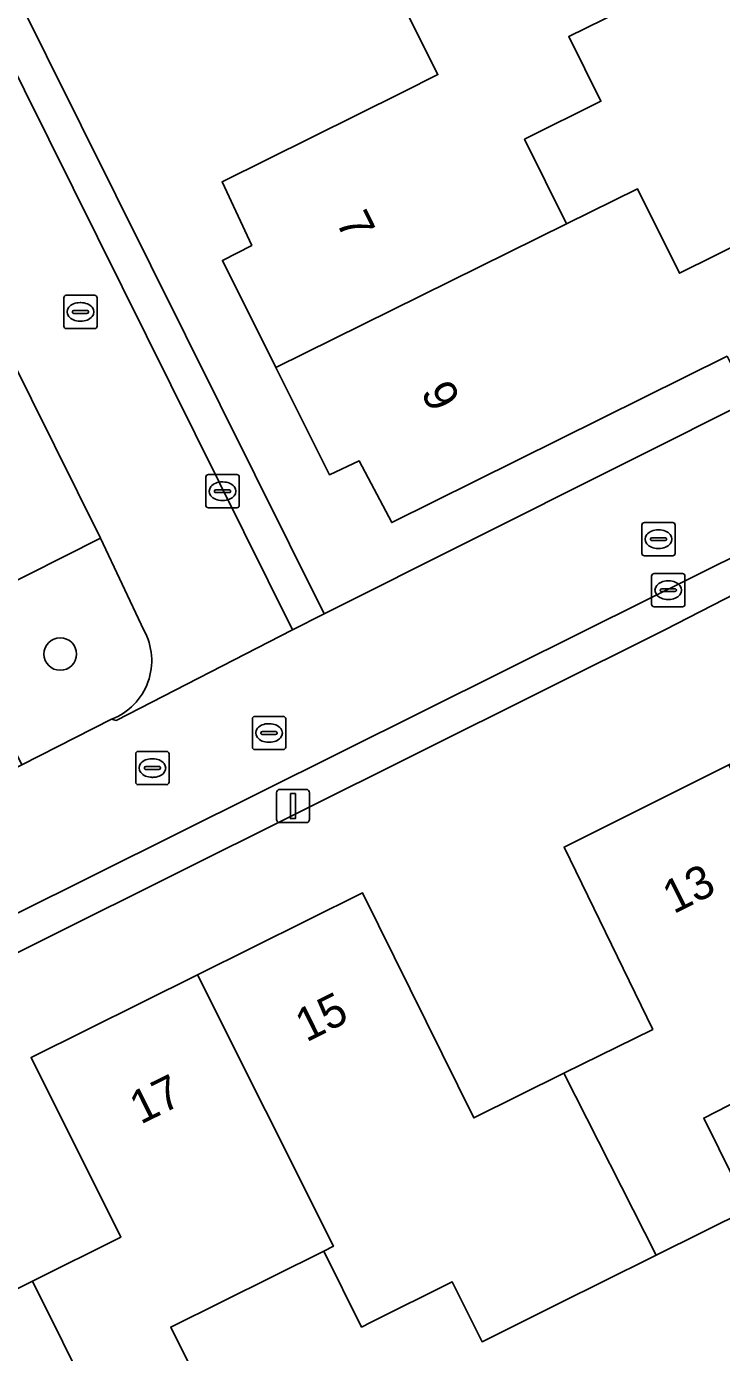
# Model space of a CAD drawing. Extents: x 157320 to 158835, y 386650 to 388491.
# Drawn here: x 157624.59 to 157645.47, y 387728.28 to 387768.13 of the extents above; entities that cross this region are included whole.
import ezdxf

# ---------------------------------------------------------------- set-up
doc = ezdxf.new("R2010")
doc.units = 0
for name, color, linetype in [('IMGEO_Boom', 7, 'Continuous'), ('IMGEO_Brandkraan', 7, 'Continuous'), ('IMGEO_Erf', 7, 'Continuous'), ('IMGEO_Groenvoorziening', 7, 'Continuous'), ('IMGEO_Kolk', 7, 'Continuous'), ('IMGEO_Lichtmast', 7, 'Continuous'), ('IMGEO_Pand', 7, 'Continuous'), ('IMGEO_Pand_nummerreeks', 7, 'Continuous'), ('IMGEO_Parkeervlak_open', 7, 'Continuous'), ('IMGEO_Rijbaan_lokaal_open', 7, 'Continuous'), ('IMGEO_Rioolput', 7, 'Continuous'), ('IMGEO_Voetpad_open', 7, 'Continuous')]:
    doc.layers.add(name, color=color, linetype=linetype)

msp = doc.modelspace()

# ---------------------------------------------------------------- linework, layer by layer
at = {"layer": 'IMGEO_Boom'}
msp.add_circle((157625.604, 387749.274), 0.489, dxfattribs=at)
at = {"layer": 'IMGEO_Brandkraan'}
for p, q in [((157629.98, 387753.741), (157629.98, 387754.593)), ((157630.055, 387754.667), (157630.907, 387754.667)), ((157630.981, 387754.593), (157630.981, 387753.741)), ((157630.239, 387754.161), (157630.239, 387754.173)), ((157630.677, 387754.124), (157630.279, 387754.124)), ((157630.282, 387754.21), (157630.68, 387754.21)), ((157630.468, 387754.447), (157630.493, 387754.447)), ((157630.723, 387754.173), (157630.723, 387754.161)), ((157630.907, 387753.667), (157630.055, 387753.667)), ((157630.491, 387753.887), (157630.466, 387753.887)), ((157643.447, 387751.693), (157644.299, 387751.693)), ((157643.372, 387750.767), (157643.372, 387751.619)), ((157643.86, 387751.473), (157643.885, 387751.473)), ((157644.373, 387751.619), (157644.373, 387750.767)), ((157643.631, 387751.187), (157643.631, 387751.199)), ((157644.069, 387751.15), (157643.671, 387751.15)), ((157643.674, 387751.236), (157644.072, 387751.236)), ((157643.883, 387750.913), (157643.858, 387750.913)), ((157644.115, 387751.199), (157644.115, 387751.187)), ((157644.299, 387750.693), (157643.447, 387750.693))]:
    msp.add_line(p, q, dxfattribs=at)
for points in [[(157629.98, 387753.741), (157629.98, 387754.593)], [(157630.055, 387754.667), (157630.907, 387754.667)], [(157630.981, 387754.593), (157630.981, 387753.741)], [(157630.907, 387753.667), (157630.055, 387753.667)], [(157643.447, 387751.693), (157644.299, 387751.693)], [(157643.372, 387750.767), (157643.372, 387751.619)], [(157644.373, 387751.619), (157644.373, 387750.767)], [(157644.299, 387750.693), (157643.447, 387750.693)]]:
    msp.add_lwpolyline(points, dxfattribs=at)
for centre, radius, start, end in [((157630.057, 387754.591), 0.0765, 91.552, 178.448), ((157630.057, 387754.591), 0.0765, 91.552, 178.448), ((157630.905, 387754.591), 0.0765, 1.552, 88.448), ((157630.905, 387754.591), 0.0765, 1.552, 88.448), ((157630.279, 387754.17), 0.0403, 85.8775, 175.7526), ((157630.276, 387754.16), 0.0366, 178.938, 274.7102), ((157630.68, 387754.167), 0.043, 264.8664, 352.4533), ((157630.684, 387754.172), 0.0386, 1.7309, 96.639), ((157630.057, 387753.743), 0.0765, 181.552, 268.448), ((157630.057, 387753.743), 0.0765, 181.552, 268.448), ((157630.905, 387753.743), 0.0765, 271.552, 358.448), ((157630.905, 387753.743), 0.0765, 271.552, 358.448), ((157643.449, 387751.617), 0.0765, 91.552, 178.448), ((157643.449, 387751.617), 0.0765, 91.552, 178.448), ((157644.297, 387751.617), 0.0765, 1.552, 88.448), ((157644.297, 387751.617), 0.0765, 1.552, 88.448), ((157643.671, 387751.196), 0.0403, 85.8775, 175.7526), ((157643.668, 387751.186), 0.0366, 178.938, 274.7102), ((157644.072, 387751.193), 0.043, 264.8664, 352.4533), ((157644.076, 387751.198), 0.0386, 1.7309, 96.639), ((157643.449, 387750.769), 0.0765, 181.552, 268.448), ((157643.449, 387750.769), 0.0765, 181.552, 268.448), ((157644.297, 387750.769), 0.0765, 271.552, 358.448), ((157644.297, 387750.769), 0.0765, 271.552, 358.448)]:
    msp.add_arc(centre, radius, start, end, dxfattribs=at)
for centre, major_axis, ratio, start_param, end_param in [((157630.467, 387754.167), (-0.387, 0.002), 0.722429, 4.712389, 7.853982), ((157630.492, 387754.167), (-0.39, 0.002), 0.717154, 1.570796, 4.712389), ((157643.859, 387751.193), (-0.387, 0.002), 0.722429, 4.712389, 7.853982), ((157643.884, 387751.193), (-0.39, 0.002), 0.717154, 1.570796, 4.712389)]:
    msp.add_ellipse(centre, major_axis=major_axis, ratio=ratio, start_param=start_param, end_param=end_param, dxfattribs=at)
at = {"layer": 'IMGEO_Erf'}
for points in [[(157617.003, 387800.065), (157607.442, 387791.699), (157617.562, 387771.351), (157622.058, 387773.543), (157633.531, 387750.485), (157646.783, 387757.12), (157649.389, 387756.267), (157653.16, 387758.176), (157651.72, 387761.079), (157657.916, 387764.123), (157659.333, 387761.239), (157658.906, 387762.988), (157655.208, 387778.141), (157652.933, 387782.468), (157652.411, 387783.461), (157651.028, 387786.092), (157650.531, 387787.038), (157665.567, 387800.286)], [(157645.641, 387758.23), (157635.566, 387753.223), (157634.586, 387755.08), (157633.69, 387754.66), (157632.083, 387757.881), (157630.476, 387761.103), (157631.36, 387761.554), (157630.466, 387763.461), (157635.875, 387766.154), (157636.949, 387766.689), (157635.589, 387769.418)], [(157643.476, 387769.12), (157640.882, 387767.829), (157641.847, 387765.886), (157639.556, 387764.746), (157640.819, 387762.206), (157642.944, 387763.258), (157644.207, 387760.72), (157646.33, 387761.775)], [(157651.656, 387754.009), (157650.874, 387753.619), (157650.828, 387753.596), (157648.407, 387752.387), (157643.767, 387750), (157603.173, 387729.76)], [(157610.727, 387726.901), (157609.424, 387729.524), (157614.417, 387732.007), (157619.375, 387734.473), (157622.075, 387729.075), (157624.774, 387730.424), (157627.429, 387731.752), (157624.73, 387737.151), (157629.73, 387739.636), (157634.684, 387742.098), (157638.027, 387735.334), (157640.738, 387736.674), (157643.403, 387737.991), (157640.74, 387743.47), (157645.692, 387745.943), (157650.678, 387748.434), (157653.266, 387743.255), (157658.319, 387746.979), (157657.144, 387748.592), (157657.386, 387748.771), (157656.565, 387750), (157653.879, 387753.597)], [(157663.207, 387727.974), (157662.074, 387729.532), (157656.171, 387737.646), (157655.954, 387737.484), (157654.025, 387739.999), (157649.776, 387737.814), (157644.937, 387735.326), (157646.295, 387732.595), (157643.504, 387731.206), (157641.819, 387730.367), (157640.726, 387729.823), (157638.277, 387728.604), (157637.382, 387730.402), (157634.95, 387729.191), (157634.659, 387729.046), (157633.522, 387731.331), (157628.926, 387729.044), (157630.275, 387726.331)]]:
    msp.add_lwpolyline(points, dxfattribs=at)
at = {"layer": 'IMGEO_Groenvoorziening'}
msp.add_lwpolyline([(157628.116, 387749.992), (157626.816, 387752.753), (157622.442, 387750.552), (157622.242, 387750.41), (157622.445, 387750), (157624.452, 387745.948), (157627.148, 387747.314)], dxfattribs=at)
msp.add_arc((157626.464, 387749.075), 1.889, 291.2162, 29.0376, dxfattribs=at)
at = {"layer": 'IMGEO_Kolk'}
for p, q in [((157625.785, 387760.056), (157626.637, 387760.056)), ((157625.71, 387759.13), (157625.71, 387759.982)), ((157626.198, 387759.836), (157626.223, 387759.836)), ((157626.711, 387759.982), (157626.711, 387759.13)), ((157625.969, 387759.55), (157625.969, 387759.562)), ((157626.407, 387759.513), (157626.009, 387759.513)), ((157626.012, 387759.599), (157626.41, 387759.599)), ((157626.221, 387759.276), (157626.196, 387759.276)), ((157626.453, 387759.562), (157626.453, 387759.55)), ((157626.637, 387759.056), (157625.785, 387759.056)), ((157643.078, 387752.299), (157643.078, 387753.151)), ((157643.153, 387753.225), (157644.005, 387753.225)), ((157643.566, 387753.005), (157643.591, 387753.005)), ((157644.079, 387753.151), (157644.079, 387752.299)), ((157643.337, 387752.719), (157643.337, 387752.731)), ((157643.775, 387752.682), (157643.377, 387752.682)), ((157643.38, 387752.768), (157643.778, 387752.768)), ((157643.821, 387752.731), (157643.821, 387752.719)), ((157644.005, 387752.225), (157643.153, 387752.225)), ((157643.589, 387752.445), (157643.564, 387752.445)), ((157631.376, 387746.475), (157631.376, 387747.327)), ((157631.451, 387747.401), (157632.303, 387747.401)), ((157632.377, 387747.327), (157632.377, 387746.475)), ((157631.635, 387746.895), (157631.635, 387746.907)), ((157631.678, 387746.944), (157632.076, 387746.944)), ((157631.864, 387747.181), (157631.889, 387747.181)), ((157632.119, 387746.907), (157632.119, 387746.895)), ((157632.073, 387746.858), (157631.675, 387746.858)), ((157631.887, 387746.621), (157631.862, 387746.621)), ((157632.303, 387746.401), (157631.451, 387746.401))]:
    msp.add_line(p, q, dxfattribs=at)
for points in [[(157625.785, 387760.056), (157626.637, 387760.056)], [(157625.71, 387759.13), (157625.71, 387759.982)], [(157626.711, 387759.982), (157626.711, 387759.13)], [(157626.637, 387759.056), (157625.785, 387759.056)], [(157643.078, 387752.299), (157643.078, 387753.151)], [(157643.153, 387753.225), (157644.005, 387753.225)], [(157644.079, 387753.151), (157644.079, 387752.299)], [(157644.005, 387752.225), (157643.153, 387752.225)], [(157631.376, 387746.475), (157631.376, 387747.327)], [(157631.451, 387747.401), (157632.303, 387747.401)], [(157632.377, 387747.327), (157632.377, 387746.475)], [(157632.303, 387746.401), (157631.451, 387746.401)]]:
    msp.add_lwpolyline(points, dxfattribs=at)
for centre, radius, start, end in [((157625.787, 387759.98), 0.0765, 91.552, 178.448), ((157625.787, 387759.98), 0.0765, 91.552, 178.448), ((157626.635, 387759.98), 0.0765, 1.552, 88.448), ((157626.635, 387759.98), 0.0765, 1.552, 88.448), ((157626.009, 387759.559), 0.0403, 85.8775, 175.7526), ((157626.006, 387759.549), 0.0366, 178.938, 274.7102), ((157626.41, 387759.556), 0.043, 264.8664, 352.4533), ((157626.414, 387759.561), 0.0386, 1.7309, 96.639), ((157625.787, 387759.132), 0.0765, 181.552, 268.448), ((157625.787, 387759.132), 0.0765, 181.552, 268.448), ((157626.635, 387759.132), 0.0765, 271.552, 358.448), ((157626.635, 387759.132), 0.0765, 271.552, 358.448), ((157643.155, 387753.149), 0.0765, 91.552, 178.448), ((157643.155, 387753.149), 0.0765, 91.552, 178.448), ((157644.003, 387753.149), 0.0765, 1.552, 88.448), ((157644.003, 387753.149), 0.0765, 1.552, 88.448), ((157643.377, 387752.728), 0.0403, 85.8775, 175.7526), ((157643.374, 387752.718), 0.0366, 178.938, 274.7102), ((157643.778, 387752.725), 0.043, 264.8664, 352.4533), ((157643.782, 387752.73), 0.0386, 1.7309, 96.639), ((157643.155, 387752.301), 0.0765, 181.552, 268.448), ((157643.155, 387752.301), 0.0765, 181.552, 268.448), ((157644.003, 387752.301), 0.0765, 271.552, 358.448), ((157644.003, 387752.301), 0.0765, 271.552, 358.448), ((157631.453, 387747.325), 0.0765, 91.552, 178.448), ((157631.453, 387747.325), 0.0765, 91.552, 178.448), ((157632.301, 387747.325), 0.0765, 1.552, 88.448), ((157632.301, 387747.325), 0.0765, 1.552, 88.448), ((157631.675, 387746.904), 0.0403, 85.8775, 175.7526), ((157631.672, 387746.894), 0.0366, 178.938, 274.7102), ((157632.076, 387746.901), 0.043, 264.8664, 352.4533), ((157632.08, 387746.906), 0.0386, 1.7309, 96.639), ((157631.453, 387746.477), 0.0765, 181.552, 268.448), ((157631.453, 387746.477), 0.0765, 181.552, 268.448), ((157632.301, 387746.477), 0.0765, 271.552, 358.448), ((157632.301, 387746.477), 0.0765, 271.552, 358.448)]:
    msp.add_arc(centre, radius, start, end, dxfattribs=at)
for centre, major_axis, ratio, start_param, end_param in [((157626.197, 387759.556), (-0.387, 0.002), 0.722429, 4.712389, 7.853982), ((157626.222, 387759.556), (-0.39, 0.002), 0.717154, 1.570796, 4.712389), ((157643.565, 387752.725), (-0.387, 0.002), 0.722429, 4.712389, 7.853982), ((157643.59, 387752.725), (-0.39, 0.002), 0.717154, 1.570796, 4.712389), ((157631.863, 387746.901), (-0.387, 0.002), 0.722429, 4.712389, 7.853982), ((157631.888, 387746.901), (-0.39, 0.002), 0.717154, 1.570796, 4.712389)]:
    msp.add_ellipse(centre, major_axis=major_axis, ratio=ratio, start_param=start_param, end_param=end_param, dxfattribs=at)
at = {"layer": 'IMGEO_Lichtmast'}
for p, q in [((157632.099, 387744.306), (157632.099, 387745.106)), ((157632.099, 387745.106), (157632.099, 387744.306)), ((157632.199, 387745.206), (157632.989, 387745.206)), ((157632.989, 387745.206), (157632.199, 387745.206)), ((157633.089, 387745.106), (157633.089, 387744.306)), ((157633.089, 387744.306), (157633.089, 387745.106)), ((157632.989, 387744.206), (157632.199, 387744.206)), ((157632.199, 387744.206), (157632.989, 387744.206))]:
    msp.add_line(p, q, dxfattribs=at)
msp.add_lwpolyline([(157632.519, 387745.081), (157632.669, 387745.081), (157632.669, 387744.331), (157632.519, 387744.331), (157632.519, 387745.081)], dxfattribs=at)
for centre, start, end in [((157632.199, 387745.106), 90, 180), ((157632.199, 387745.106), 90, 180), ((157632.989, 387745.106), 0, 90), ((157632.989, 387745.106), 360, 90), ((157632.199, 387744.306), 180, 270), ((157632.199, 387744.306), 180, 270), ((157632.989, 387744.306), 270, 0), ((157632.989, 387744.306), 270, 0)]:
    msp.add_arc(centre, 0.1, start, end, dxfattribs=at)
at = {"layer": 'IMGEO_Pand'}
for points in [[(157640.819, 387762.206), (157639.556, 387764.746), (157641.847, 387765.886), (157640.882, 387767.829), (157643.476, 387769.12), (157641.807, 387772.475), (157635.589, 387769.418), (157636.949, 387766.689), (157635.875, 387766.154), (157630.466, 387763.461), (157631.36, 387761.554), (157630.476, 387761.103), (157632.083, 387757.881)], [(157645.641, 387758.23), (157645.784, 387757.944), (157647.691, 387758.893), (157646.33, 387761.775), (157644.207, 387760.72), (157642.944, 387763.258), (157640.819, 387762.206), (157632.083, 387757.881), (157633.69, 387754.66), (157634.586, 387755.08), (157635.566, 387753.223)], [(157645.692, 387745.943), (157640.74, 387743.47), (157643.403, 387737.991), (157640.738, 387736.674), (157643.504, 387731.206), (157646.295, 387732.595), (157644.937, 387735.326), (157649.776, 387737.814)], [(157640.738, 387736.674), (157638.027, 387735.334), (157634.684, 387742.098), (157629.73, 387739.636), (157633.809, 387731.474), (157633.522, 387731.331), (157634.659, 387729.046), (157634.95, 387729.191), (157637.382, 387730.402), (157638.277, 387728.604), (157640.726, 387729.823), (157641.819, 387730.367), (157643.504, 387731.206)], [(157629.73, 387739.636), (157624.73, 387737.151), (157627.429, 387731.752), (157624.774, 387730.424), (157627.495, 387724.947), (157630.275, 387726.331), (157628.926, 387729.044), (157633.522, 387731.331), (157633.809, 387731.474)], [(157618.484, 387723.846), (157621.026, 387725.111), (157621.997, 387723.16), (157622.993, 387722.706), (157624.706, 387723.559), (157627.495, 387724.947), (157624.774, 387730.424), (157622.075, 387729.075), (157619.375, 387734.473), (157614.417, 387732.007)]]:
    msp.add_lwpolyline(points, close=True, dxfattribs=at)
at = {"layer": 'IMGEO_Parkeervlak_open'}
msp.add_lwpolyline([(157626.816, 387752.753), (157621.29, 387763.877), (157616.917, 387761.684), (157622.442, 387750.552)], close=True, dxfattribs=at)
at = {"layer": 'IMGEO_Rijbaan_lokaal_open'}
for points in [[(157627.148, 387747.314), (157627.283, 387747.278), (157632.586, 387750), (157621.591, 387772.124), (157617.099, 387769.917), (157606.621, 387790.971)], [(157604.923, 387785.502), (157613.565, 387768.163), (157614.025, 387767.239), (157614.222, 387767.173), (157620.74, 387764.999), (157621.29, 387763.877), (157626.816, 387752.753), (157628.116, 387749.992)], [(157650.353, 387754.548), (157649.389, 387756.267), (157646.783, 387757.12), (157633.531, 387750.485), (157632.586, 387750), (157627.283, 387747.278), (157627.148, 387747.314), (157624.452, 387745.948), (157609.428, 387738.45), (157605.783, 387736.635)], [(157602.045, 387730.396), (157641.414, 387750), (157646.334, 387752.45), (157650.353, 387754.548)]]:
    msp.add_lwpolyline(points, dxfattribs=at)
msp.add_arc((157626.464, 387749.075), 1.889, 291.2162, 29.0376, dxfattribs=at)
at = {"layer": 'IMGEO_Rioolput'}
for p, q in [((157627.872, 387745.422), (157627.872, 387746.274)), ((157627.947, 387746.348), (157628.799, 387746.348)), ((157628.36, 387746.128), (157628.385, 387746.128)), ((157628.873, 387746.274), (157628.873, 387745.422)), ((157628.131, 387745.842), (157628.131, 387745.854)), ((157628.569, 387745.805), (157628.171, 387745.805)), ((157628.174, 387745.891), (157628.572, 387745.891)), ((157628.615, 387745.854), (157628.615, 387745.842)), ((157628.799, 387745.348), (157627.947, 387745.348)), ((157628.383, 387745.568), (157628.358, 387745.568))]:
    msp.add_line(p, q, dxfattribs=at)
for points in [[(157627.872, 387745.422), (157627.872, 387746.274)], [(157627.947, 387746.348), (157628.799, 387746.348)], [(157628.873, 387746.274), (157628.873, 387745.422)], [(157628.799, 387745.348), (157627.947, 387745.348)]]:
    msp.add_lwpolyline(points, dxfattribs=at)
for centre, radius, start, end in [((157627.949, 387746.272), 0.0765, 91.552, 178.448), ((157627.949, 387746.272), 0.0765, 91.552, 178.448), ((157628.797, 387746.272), 0.0765, 1.552, 88.448), ((157628.797, 387746.272), 0.0765, 1.552, 88.448), ((157628.171, 387745.851), 0.0403, 85.8775, 175.7526), ((157628.168, 387745.841), 0.0366, 178.938, 274.7102), ((157628.572, 387745.848), 0.043, 264.8664, 352.4533), ((157628.576, 387745.853), 0.0386, 1.7309, 96.639), ((157627.949, 387745.424), 0.0765, 181.552, 268.448), ((157627.949, 387745.424), 0.0765, 181.552, 268.448), ((157628.797, 387745.424), 0.0765, 271.552, 358.448), ((157628.797, 387745.424), 0.0765, 271.552, 358.448)]:
    msp.add_arc(centre, radius, start, end, dxfattribs=at)
for centre, major_axis, ratio, start_param, end_param in [((157628.359, 387745.848), (-0.387, 0.002), 0.722429, 4.712389, 7.853982), ((157628.384, 387745.848), (-0.39, 0.002), 0.717154, 1.570796, 4.712389)]:
    msp.add_ellipse(centre, major_axis=major_axis, ratio=ratio, start_param=start_param, end_param=end_param, dxfattribs=at)
at = {"layer": 'IMGEO_Voetpad_open'}
msp.add_lwpolyline([(157607.442, 387791.699), (157606.621, 387790.971), (157617.099, 387769.917), (157621.591, 387772.124), (157632.586, 387750), (157633.531, 387750.485), (157622.058, 387773.543), (157617.562, 387771.351)], close=True, dxfattribs=at)
for points in [[(157643.767, 387750), (157648.407, 387752.387), (157650.828, 387753.596), (157650.353, 387754.548), (157646.334, 387752.45), (157641.414, 387750), (157602.045, 387730.396)], [(157603.173, 387729.76), (157643.767, 387750)]]:
    msp.add_lwpolyline(points, dxfattribs=at)

# ---------------------------------------------------------------- texts
at = {"layer": 'IMGEO_Pand_nummerreeks'}
for s, rotation, p in [('7', 296.4799, (157633.874, 387762.272)), ('9', 296.4819, (157636.424, 387757.152)), ('13', 26.542, (157644.032, 387741.449)), ('15', 26.4248, (157632.996, 387737.596)), ('17', 26.4248, (157628.019, 387735.123))]:
    msp.add_text(s, height=1, rotation=rotation, dxfattribs=at).set_placement(p)

doc.saveas('drawing.dxf')
